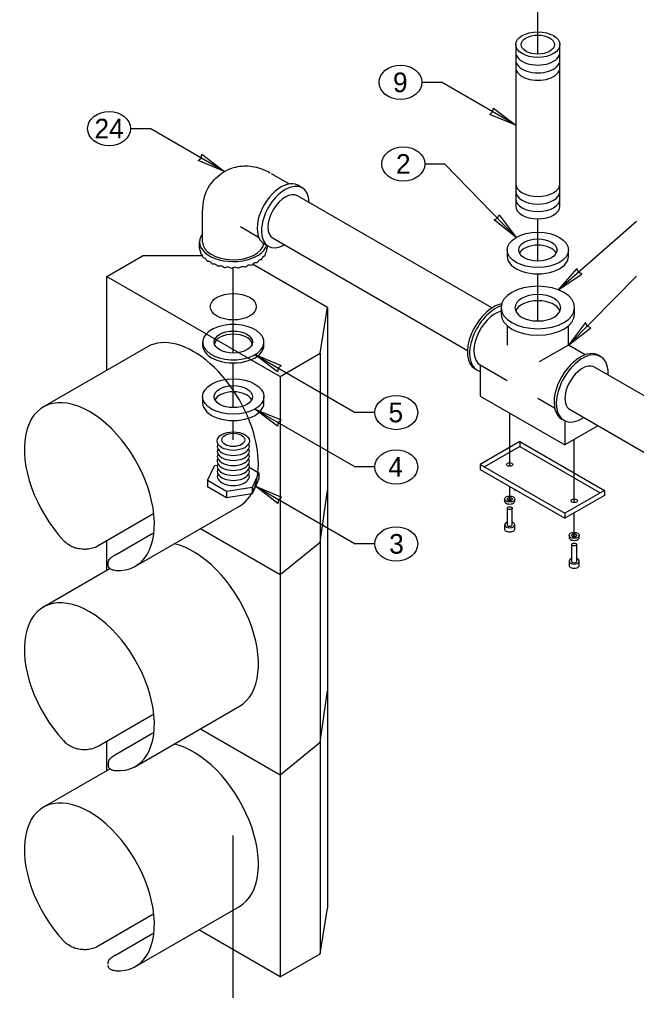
# Model space of a CAD drawing. Extents: x 99862 to 104211, y 98939 to 105076.
# Drawn here: x 101611 to 102115, y 103854 to 104647 of the extents above; entities that cross this region are included whole.
import ezdxf

# ---------------------------------------------------------------- set-up
doc = ezdxf.new("R2010")
doc.units = 0
for name, color, linetype in [('Level 11', 7, 'Continuous'), ('Level 15', 7, 'Continuous'), ('Level 19', 7, 'Continuous'), ('Level 2', 7, 'Continuous'), ('Level 20', 7, 'Continuous'), ('Level 26', 7, 'Continuous'), ('Level 3', 7, 'Continuous'), ('Level 4', 7, 'Continuous'), ('Level 5', 7, 'Continuous'), ('Level 6', 7, 'Continuous'), ('Level 7', 7, 'Continuous'), ('Level 9', 7, 'Continuous')]:
    doc.layers.add(name, color=color, linetype=linetype)

msp = doc.modelspace()

# ---------------------------------------------------------------- linework, layer by layer
at = {"layer": 'Level 11'}
for p, q in [((102009.05, 104458.67), (102009.05, 104453.57)), ((102059.05, 104453.57), (102059.05, 104458.67)), ((101760.68, 104383.46), (101760.68, 104380.91)), ((101810.68, 104380.91), (101810.68, 104383.46)), ((101760.68, 104339.03), (101760.68, 104333.93)), ((101810.68, 104333.93), (101810.68, 104339.03)), ((102006.95, 104255.47), (102006.95, 104253.77)), ((102015.28, 104253.77), (102015.28, 104255.47)), ((102009.03, 104248.02), (102009.03, 104234.41)), ((102013.2, 104234.41), (102013.2, 104248.02)), ((102006.95, 104234.41), (102006.95, 104231.01)), ((102015.28, 104231.01), (102015.28, 104234.41)), ((102059.5, 104225.83), (102059.5, 104224.13)), ((102061.59, 104218.37), (102061.59, 104204.76)), ((102065.75, 104204.76), (102065.75, 104218.37)), ((102067.84, 104224.13), (102067.84, 104225.83)), ((102059.5, 104204.76), (102059.5, 104201.36)), ((102067.84, 104201.36), (102067.84, 104204.76))]:
    msp.add_line(p, q, dxfattribs=at)
for centre, major_axis in [((102034.05, 104458.67), (15.62, 0)), ((101785.68, 104383.46), (15.62, 0)), ((101785.68, 104339.03), (15.62, 0)), ((102011.11, 104255.47), (-4.17, 0)), ((102011.11, 104255.47), (-2.08, 0)), ((102011.11, 104248.02), (-2.08, 0)), ((102063.67, 104225.83), (-4.17, 0)), ((102063.67, 104225.83), (-2.08, 0)), ((102063.67, 104218.37), (-2.08, 0))]:
    msp.add_ellipse(centre, major_axis=major_axis, ratio=0.57735, dxfattribs=at)
for centre, major_axis, start_param, end_param in [((102034.05, 104453.57), (-15.62, 0), 3.428349, 5.996429), ((102034.05, 104453.57), (-25, 0), 6.283185, 9.424778), ((101785.68, 104380.91), (-15.62, 0), 3.28349, 6.141288), ((101785.68, 104380.91), (-25, 0), 0, 3.141593), ((101785.68, 104333.93), (-15.62, 0), 3.428349, 5.996429), ((101785.68, 104333.93), (-25, 0), 6.283185, 9.424778), ((102011.11, 104253.77), (-4.17, 0), 0, 3.141593), ((102011.11, 104253.77), (-2.08, 0), 3.926991, 5.497787), ((102011.11, 104234.41), (-4.17, 0), 5.235988, 10.471976), ((102011.11, 104234.41), (-2.08, 0), 0, 3.141593), ((102011.11, 104231.01), (-4.17, 0), 6.283185, 9.424778), ((102063.67, 104224.13), (-4.17, 0), 0, 3.141593), ((102063.67, 104224.13), (-2.08, 0), 3.926991, 5.497787), ((102063.67, 104204.76), (-4.17, 0), 5.235988, 10.471976), ((102063.67, 104204.76), (-2.08, 0), 0, 3.141593), ((102063.67, 104201.36), (-4.17, 0), 6.283185, 9.424778)]:
    msp.add_ellipse(centre, major_axis=major_axis, ratio=0.57735, start_param=start_param, end_param=end_param, dxfattribs=at)
at = {"layer": 'Level 15'}
for p, q in [((102034.05, 104618.38), (102034.05, 104657.53)), ((101939.51, 104595.41), (101955.51, 104595.41)), ((102016.05, 104560.46), (101955.51, 104595.41)), ((101701.82, 104557.65), (101717.82, 104557.65)), ((101778.36, 104522.7), (101717.82, 104557.65)), ((101941.83, 104528.84), (101957.83, 104528.84)), ((102016.37, 104468.88), (101957.83, 104528.84)), ((102034.05, 104449.65), (102034.05, 104483.99)), ((102050.71, 104426.15), (102114.56, 104482.17)), ((101785.68, 104374.44), (101785.68, 104444.3)), ((102034.05, 104401.09), (102034.05, 104439.14)), ((102034.05, 104400.71), (102034.05, 104439.14)), ((102059.05, 104381.05), (102114.56, 104437.35)), ((101803.35, 104373.25), (101885.08, 104326.06)), ((101785.68, 104330.01), (101785.68, 104366.47)), ((101803.35, 104328.82), (101885.08, 104281.64)), ((101901.08, 104326.06), (101885.08, 104326.06)), ((102011.11, 104282.2), (102011.11, 104325.62)), ((101785.68, 104303.75), (101785.68, 104319.49)), ((102063.67, 104252.55), (102063.67, 104304.11)), ((101901.08, 104281.64), (101885.08, 104281.64)), ((101803.79, 104265.84), (101885.08, 104218.9)), ((102011.11, 104254.27), (102011.11, 104265.76)), ((102063.67, 104224.63), (102063.67, 104244.25)), ((101901.08, 104218.9), (101885.08, 104218.9)), ((101785.68, 103791.46), (101785.68, 103980.92))]:
    msp.add_line(p, q, dxfattribs=at)
for points in [[(102016.05, 104560.46), (101994.78, 104569.29), (101997.19, 104571.35), (101997.77, 104574.46)], [(101778.36, 104522.7), (101757.09, 104531.53), (101759.5, 104533.59), (101760.08, 104536.7)], [(102016.37, 104468.88), (101998.29, 104483.13), (102001.16, 104484.46), (102002.56, 104487.3)], [(102050.71, 104426.15), (102069.84, 104438.96), (102067.08, 104440.51), (102065.9, 104443.45)], [(102059.05, 104381.05), (102077.2, 104395.21), (102074.34, 104396.56), (102072.95, 104399.41)], [(101803.35, 104373.25), (101824.62, 104364.42), (101822.21, 104362.36), (101821.63, 104359.25)], [(101803.35, 104328.82), (101824.62, 104320), (101822.21, 104317.94), (101821.63, 104314.82)], [(101803.79, 104265.84), (101825.05, 104257.01), (101822.64, 104254.95), (101822.07, 104251.84)]]:
    msp.add_lwpolyline(points, close=True, dxfattribs=at)
at = {"layer": 'Level 19'}
for p, q in [((101856.62, 104220.39), (101862.49, 104262.39)), ((101823.85, 104193.91), (101856.62, 104220.39)), ((101856.62, 104057.1), (101862.49, 104099.09)), ((101823.85, 104030.61), (101856.62, 104057.1))]:
    msp.add_line(p, q, dxfattribs=at)
at = {"layer": 'Level 2'}
for p, q in [((101806.59, 104276.98), (101800.99, 104264.91)), ((101780.07, 104261.67), (101764.76, 104270.51)), ((101800.99, 104264.91), (101780.07, 104261.67)), ((101780.07, 104261.67), (101780.07, 104256.57)), ((101800.99, 104264.91), (101800.99, 104259.8))]:
    msp.add_line(p, q, dxfattribs=at)
for centre, major_axis in [((102034.05, 104458.67), (25, 0)), ((101785.68, 104303.75), (-9.38, 0))]:
    msp.add_ellipse(centre, major_axis=major_axis, ratio=0.57735, dxfattribs=at)
for centre, start_param, end_param in [((101785.68, 104298.65), 2.86885, 6.555928), ((101785.68, 104290.4), 2.86338, 6.561398), ((101785.68, 104294.57), 2.86885, 6.555928), ((101785.68, 104282.32), 2.86885, 6.555928), ((101785.68, 104286.4), 2.874311, 6.550467), ((101785.68, 104278.24), 2.86885, 6.555928)]:
    msp.add_ellipse(centre, major_axis=(13.12, 0), ratio=0.57735, start_param=start_param, end_param=end_param, dxfattribs=at)
at = {"layer": 'Level 20'}
for p, q in [((101816.61, 104521.02), (101831.34, 104512.52)), ((101996.63, 104411.32), (101838.1, 104502.84)), ((101760.68, 104465.11), (101760.68, 104489.61)), ((101758.18, 104460.18), (101758.18, 104465.11)), ((101818.1, 104468.2), (101976.63, 104376.68)), ((101813.18, 104462.39), (101813.18, 104460.18)), ((102240.55, 104270.49), (102080.29, 104363.02)), ((102060.29, 104328.38), (102220.55, 104235.85))]:
    msp.add_line(p, q, dxfattribs=at)
for centre in [(101922.01, 104595.41), (101684.32, 104557.65), (101924.33, 104528.84), (101918.58, 104326.06), (101918.58, 104281.64), (101918.58, 104218.9)]:
    msp.add_ellipse(centre, major_axis=(-17.5, 0), ratio=0.8, dxfattribs=at)
for centre, major_axis, ratio, start_param, end_param in [((101828.1, 104485.52), (13.75, 23.82), 0.57735, 5.526729, 10.181234), ((101828.1, 104485.52), (-10, -17.32), 0.57735, 3.141593, 6.283185), ((101785.68, 104460.72), (-27.03, -5.37), 0.947565, 6.097095, 6.149455), ((101785.68, 104460.72), (-27.5, -1.68), 0.206802, 0.039705, 0.144424), ((101785.68, 104460.72), (25.29, -11.7), 0.922162, 3.702024, 3.806744), ((101785.68, 104460.72), (-24.52, -14.02), 0.887795, 2.305204, 2.41027), ((101785.68, 104460.72), (27.49, -2.78), 0.21596, 6.043201, 6.148266), ((101785.68, 104460.72), (-27.03, -5.37), 0.947565, 2.798769, 2.903143), ((101785.68, 104460.72), (-27.49, -3.89), 0.223561, 0.230203, 0.334923), ((101785.68, 104460.72), (24.12, -15.48), 0.853385, 4.009326, 4.114045), ((101785.68, 104460.72), (-27.46, -6), 0.252109, 0.416228, 0.520948), ((101785.68, 104460.72), (24.3, -16.43), 0.783391, 4.204501, 4.309221), ((101785.68, 104460.72), (-27.4, -7.98), 0.290225, 0.596374, 0.701094), ((101785.68, 104460.72), (24.82, -16.54), 0.715795, 4.372134, 4.476854), ((101785.68, 104460.72), (-25.11, -16.43), 0.682966, 1.726553, 1.831273), ((101785.68, 104460.72), (27.36, -8.91), 0.312139, 5.494389, 5.599109), ((101785.68, 104460.72), (-24.54, -16.55), 0.749264, 1.888318, 1.993037), ((101785.68, 104460.72), (27.43, -7.01), 0.270119, 5.671382, 5.776101), ((101785.68, 104460.72), (-24.14, -16.11), 0.818147, 2.06586, 2.17058), ((101785.68, 104460.72), (27.48, -4.96), 0.236491, 5.854579, 5.958953), ((101785.68, 104460.72), (-27.3, -9.8), 0.335596, 0.770216, 0.874936), ((101785.68, 104460.72), (25.39, -16.22), 0.650745, 4.530376, 4.635096), ((101785.68, 104460.72), (-27.14, -11.45), 0.386234, 0.938087, 1.042807), ((101785.68, 104460.72), (25.93, -15.58), 0.588004, 4.685558, 4.790278), ((101785.68, 104460.72), (-26.91, -12.9), 0.440657, 1.100807, 1.205527), ((101785.68, 104460.72), (26.39, -14.68), 0.527399, 4.840753, 4.945473), ((101785.68, 104460.72), (-26.58, -14.14), 0.497899, 1.259485, 1.364205), ((101785.68, 104460.72), (26.76, -13.55), 0.468967, 4.997892, 5.102611), ((101785.68, 104460.72), (-26.17, -15.16), 0.557438, 1.415448, 1.520168), ((101785.68, 104460.72), (27.03, -12.2), 0.413044, 5.158439, 5.263158), ((101785.68, 104460.72), (-25.67, -15.94), 0.6191, 1.570348, 1.675068), ((101785.68, 104460.72), (27.23, -10.65), 0.360362, 5.323611, 5.42833), ((102070.29, 104345.7), (10, 17.32), 0.57735, 0, 3.141593)]:
    msp.add_ellipse(centre, major_axis=major_axis, ratio=ratio, start_param=start_param, end_param=end_param, dxfattribs=at)
msp.add_open_spline([(101760.68, 104489.61), (101760.68, 104497.83), (101764.02, 104510.4), (101776.35, 104522.51), (101789.05, 104527.55), (101802.97, 104527.31), (101811.72, 104523.84), (101815.85, 104521.46)], degree=3, dxfattribs=at)
at = {"layer": 'Level 26'}
for p, q in [((101682.43, 104437.12), (101711.49, 104453.89)), ((101760.48, 104453.89), (101711.49, 104453.89)), ((101862.49, 104411.68), (101801.4, 104446.95)), ((101682.43, 104360.42), (101682.43, 104437.12)), ((101682.43, 104437.12), (101823.85, 104355.47)), ((101856.62, 104374.39), (101862.49, 104411.68)), ((101862.49, 104411.68), (101862.49, 103921.78)), ((101715.64, 104379.59), (101630.79, 104330.6)), ((101823.85, 104355.47), (101856.62, 104374.39)), ((101856.62, 104374.39), (101856.62, 103884.49)), ((101823.85, 104355.47), (101823.85, 103865.57)), ((102015.17, 104263.42), (102015.17, 104262.09)), ((101720.06, 104243.02), (101675.36, 104217.21)), ((101705.79, 104200.7), (101790.64, 104249.69)), ((101689.5, 104210.07), (101719.96, 104227.66)), ((101758.94, 104231.39), (101823.85, 104193.91)), ((101682.43, 104197.12), (101682.43, 104221.29)), ((101683.64, 104201.72), (101683.64, 104202.77)), ((101685.16, 104198.7), (101630.79, 104167.31)), ((101705.79, 104037.4), (101790.64, 104086.39)), ((101675.36, 104053.91), (101720.06, 104079.72)), ((101758.94, 104068.09), (101823.85, 104030.61)), ((101719.96, 104064.36), (101689.5, 104046.78)), ((101682.43, 104033.82), (101682.43, 104057.99)), ((101683.64, 104039.47), (101683.64, 104038.42)), ((101685.16, 104035.4), (101630.79, 104004.01)), ((101705.79, 103874.1), (101790.64, 103923.09)), ((101856.62, 103884.49), (101862.49, 103921.78)), ((101720.06, 103916.42), (101675.36, 103890.61)), ((101823.85, 103865.57), (101757.43, 103903.92)), ((101689.5, 103883.48), (101719.96, 103901.06)), ((101823.85, 103865.57), (101856.62, 103884.49))]:
    msp.add_line(p, q, dxfattribs=at)
msp.add_ellipse((101785.68, 104412.38), major_axis=(18.75, 0), ratio=0.57735, dxfattribs=at)
for centre, start_param, end_param in [((101753.14, 104314.64), 0, 3.141593), ((101668.29, 104265.65), 5.909304, 11.369456), ((101753.14, 104151.34), 0, 2.65862), ((101668.29, 104102.35), 5.909304, 11.369456), ((101753.14, 103988.04), 0, 2.65862), ((101668.29, 103939.05), 5.909304, 11.369456)]:
    msp.add_ellipse(centre, major_axis=(37.5, -64.95), ratio=0.57735, start_param=start_param, end_param=end_param, dxfattribs=at)
for points, degree in [([(101675.36, 104217.21), (101673.45, 104216.11), (101671.18, 104215.3), (101666.22, 104214.41), (101663.54, 104214.34), (101658.27, 104215.07), (101655.65, 104215.88), (101650.94, 104218.28), (101648.83, 104219.88), (101647.08, 104221.78)], 3), ([(101683.64, 104202.75), (101683.64, 104205.08), (101685.75, 104207.91), (101689.5, 104210.07)], 2), ([(101689.5, 104197.28), (101687.75, 104197.41), (101686.31, 104197.86), (101684.26, 104199.35), (101683.69, 104200.38), (101683.65, 104201.6), (101683.64, 104201.64), (101683.64, 104201.68)], 3), ([(101647.08, 104058.48), (101648.83, 104056.58), (101650.94, 104054.98), (101655.65, 104052.58), (101658.27, 104051.77), (101663.54, 104051.04), (101666.22, 104051.11), (101671.18, 104052), (101673.45, 104052.81), (101675.36, 104053.91)], 3), ([(101689.5, 104046.78), (101685.75, 104044.61), (101683.64, 104041.78), (101683.64, 104039.46)], 2), ([(101683.64, 104038.38), (101683.64, 104038.34), (101683.65, 104038.31), (101683.69, 104037.08), (101684.26, 104036.05), (101686.31, 104034.56), (101687.75, 104034.11), (101689.5, 104033.98)], 3), ([(101675.36, 103890.61), (101673.45, 103889.51), (101671.18, 103888.7), (101666.22, 103887.81), (101663.54, 103887.75), (101658.27, 103888.47), (101655.65, 103889.28), (101650.94, 103891.68), (101648.83, 103893.28), (101647.08, 103895.18)], 3), ([(101683.64, 103876.16), (101683.64, 103878.49), (101685.75, 103881.31), (101689.5, 103883.48)], 2), ([(101689.5, 103870.68), (101687.75, 103870.81), (101686.31, 103871.26), (101684.26, 103872.75), (101683.69, 103873.78), (101683.65, 103875.01), (101683.64, 103875.04), (101683.64, 103875.08)], 3)]:
    msp.add_open_spline(points, degree=degree, dxfattribs=at)
at = {"layer": 'Level 3'}
for p, q in [((101764.76, 104270.51), (101770.37, 104282.58)), ((101772.59, 104282.93), (101770.37, 104282.58)), ((101798.73, 104281.52), (101806.59, 104276.98)), ((101806.59, 104276.98), (101806.59, 104271.88)), ((101764.76, 104270.51), (101764.76, 104265.41)), ((101806.59, 104271.88), (101800.99, 104259.8)), ((101780.07, 104256.57), (101764.76, 104265.41)), ((101800.99, 104259.8), (101780.07, 104256.57))]:
    msp.add_line(p, q, dxfattribs=at)
msp.add_ellipse((101785.68, 104302.73), major_axis=(13.12, 0), ratio=0.57735, dxfattribs=at)
msp.add_ellipse((101785.68, 104274.06), major_axis=(13.12, 0), ratio=0.57735, start_param=2.862617, end_param=6.56216, dxfattribs=at)
at = {"layer": 'Level 4'}
msp.add_ellipse((101785.68, 104339.03), major_axis=(25, 0), ratio=0.57735, dxfattribs=at)
at = {"layer": 'Level 5'}
msp.add_ellipse((101785.68, 104383.46), major_axis=(25, 0), ratio=0.57735, start_param=1.690716, end_param=7.973165, dxfattribs=at)
at = {"layer": 'Level 6'}
for p, q in [((102004.05, 104411.75), (102004.05, 104410.75)), ((102004.05, 104410.75), (102004.05, 104406.42)), ((102064.05, 104406.42), (102064.05, 104411.74)), ((102009.05, 104396.85), (102009.05, 104381.05)), ((102059.05, 104381.05), (102059.05, 104396.85)), ((102059.05, 104381.05), (102035.23, 104367.3)), ((102072.73, 104373.16), (102059.05, 104381.05)), ((102085.29, 104371.68), (102083.52, 104372.7)), ((101982.81, 104361.56), (101984.58, 104360.54)), ((101987.08, 104364.87), (102009.05, 104352.19)), ((101987.08, 104364.87), (101987.08, 104339.5)), ((101987.08, 104339.5), (102056.02, 104299.7)), ((102034.05, 104337.75), (102047.73, 104329.85)), ((102053.52, 104320.74), (102055.29, 104319.72)), ((102056.02, 104319.33), (102056.02, 104299.7)), ((102082.99, 104315.27), (102056.02, 104299.7)), ((102019.37, 104302.28), (101987.08, 104283.63)), ((102019.37, 104298.28), (101990.54, 104281.63)), ((102019.37, 104302.28), (102088.31, 104262.47)), ((102019.37, 104302.28), (102019.37, 104298.28)), ((102019.37, 104298.28), (102084.85, 104260.47)), ((101987.08, 104283.63), (102056.02, 104243.83)), ((101987.08, 104283.63), (101987.08, 104279.63)), ((101987.08, 104279.63), (102056.02, 104239.83)), ((102088.31, 104262.47), (102056.02, 104243.83)), ((102088.31, 104258.47), (102056.02, 104239.83)), ((102088.31, 104262.47), (102088.31, 104258.47)), ((102056.02, 104243.83), (102056.02, 104239.83))]:
    msp.add_line(p, q, dxfattribs=at)
for centre, major_axis in [((102034.05, 104626.17), (13.5, 0)), ((102011.11, 104283.7), (-2.6, 0)), ((102063.67, 104254.06), (-2.6, 0))]:
    msp.add_ellipse(centre, major_axis=major_axis, ratio=0.57735, dxfattribs=at)
for centre, major_axis, start_param, end_param in [((102034.05, 104411.74), (30, 0), 0.000426, 6.283185), ((102034.05, 104411.52), (18.71, 0), 0.000426, 6.283185), ((102034.05, 104406.42), (-18.75, 0), 3.384387, 6.040391), ((101997.81, 104387.54), (15, 25.98), 0.470604, 3.141593), ((101999.58, 104386.52), (15, 25.98), 0.566145, 3.141593), ((101999.58, 104386.52), (12.5, 21.65), 0.529676, 3.141593), ((102034.05, 104406.42), (30, 0), 3.141593, 6.283185), ((102068.52, 104346.72), (15, 25.98), 0, 3.141593), ((102070.29, 104345.7), (15, 25.98), 5.442117, 9.424778), ((101999.58, 104386.52), (15, 25.98), 3.141593, 3.296854), ((102070.29, 104345.7), (15, 25.98), 3.141593, 3.982661)]:
    msp.add_ellipse(centre, major_axis=major_axis, ratio=0.57735, start_param=start_param, end_param=end_param, dxfattribs=at)
at = {"layer": 'Level 7'}
for p, q in [((101841.85, 104509.34), (101838.32, 104511.38)), ((101791.61, 104477.72), (101806.34, 104469.22)), ((101810.82, 104463.75), (101814.35, 104461.71))]:
    msp.add_line(p, q, dxfattribs=at)
for centre, major_axis, ratio, start_param, end_param in [((101824.57, 104487.56), (13.75, 23.82), 0.57735, 0, 3.141593), ((101785.68, 104465.11), (27.5, 0), 0.57735, 2.711893, 6.123637), ((101785.68, 104465.11), (25, 0), 0.57735, 3.141593, 6.198272), ((101785.68, 104460.72), (27.5, -0.56), 0.203365, 6.234982, 6.287342)]:
    msp.add_ellipse(centre, major_axis=major_axis, ratio=ratio, start_param=start_param, end_param=end_param, dxfattribs=at)
at = {"layer": 'Level 9'}
for p, q in [((102016.05, 104626.17), (102016.05, 104494.39)), ((102052.05, 104494.39), (102052.05, 104626.17))]:
    msp.add_line(p, q, dxfattribs=at)
msp.add_ellipse((102034.05, 104626.17), major_axis=(18, 0), ratio=0.57735, dxfattribs=at)
for centre, start_param in [((102034.05, 104619.89), 3.141588), ((102034.05, 104613.57), 3.141587), ((102034.05, 104607.44), 3.141585), ((102034.05, 104512.66), 3.141593), ((102034.05, 104506.53), 3.141593), ((102034.05, 104500.4), 3.141593), ((102034.05, 104494.39), 3.141593)]:
    msp.add_ellipse(centre, major_axis=(18, 0), ratio=0.57735, start_param=start_param, end_param=6.283185, dxfattribs=at)

# ---------------------------------------------------------------- texts
at = {"layer": 'Level 20'}
for s, p in [('9', (101915.92, 104587.42)), ('24', (101672.48, 104549.66)), ('2', (101918.34, 104520.85)), ('5', (101912.27, 104318.07)), ('4', (101912.07, 104273.64)), ('3', (101912.8, 104210.91))]:
    msp.add_text(s, height=16, dxfattribs=at).set_placement(p)

doc.saveas('drawing.dxf')
